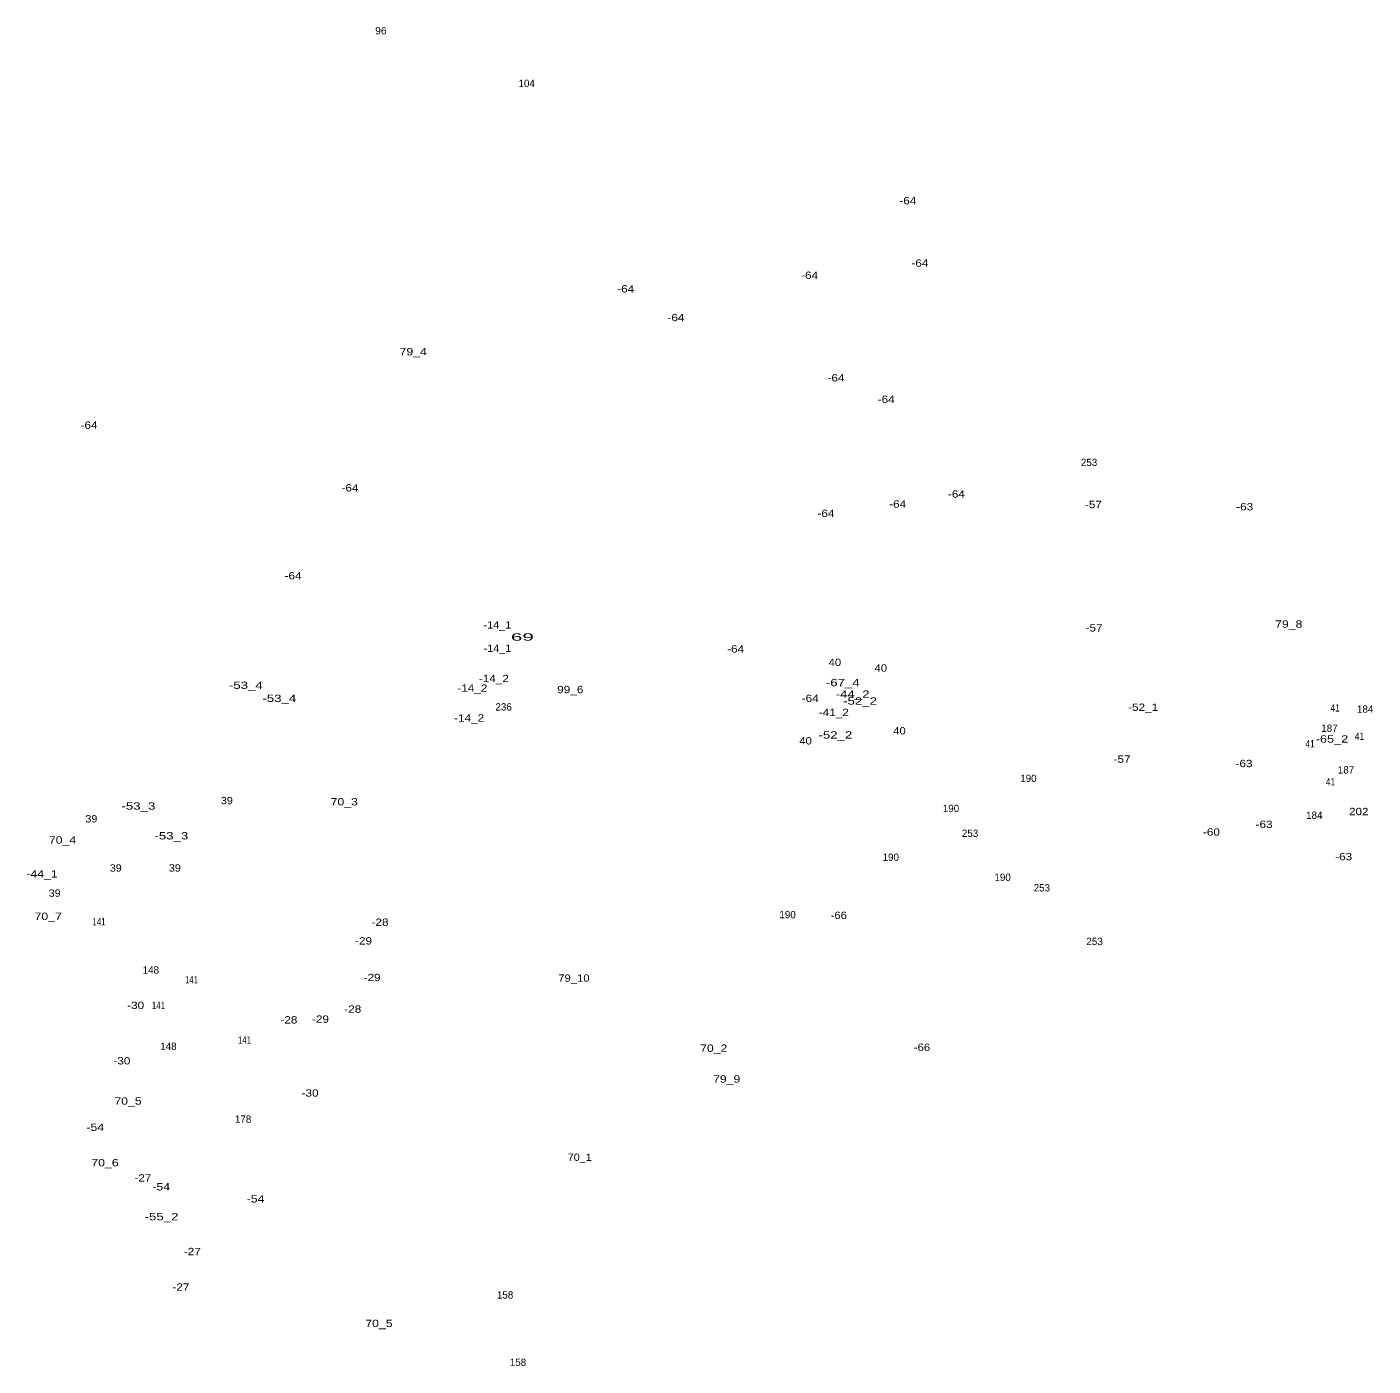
# Model space of a CAD drawing. Extents: x -659306 to -656317, y -989614 to -987663.
# Drawn here: x -657051 to -656317, y -988607 to -987877 of the extents above; entities that cross this region are included whole.
import ezdxf
from ezdxf.enums import TextEntityAlignment as Align

# ---------------------------------------------------------------- set-up
doc = ezdxf.new("R2010")
doc.units = 0
doc.header["$LTSCALE"] = 1.6
doc.layers.add('24', color=7, linetype='Continuous')

msp = doc.modelspace()

# ---------------------------------------------------------------- texts
at = {"layer": '24'}
for s, width, p in [('96', 1.05, (-656858.05, -987880.65)), ('-64', 1.2, (-656570.601, -987973.32)), ('-64', 1.2, (-656564.03, -988007.36)), ('-64', 1.2, (-656624.171, -988014.01)), ('-64', 1.2, (-656724.481, -988021.44)), ('-64', 1.2, (-656697.111, -988037.09)), ('79_4', 1.25, (-656840.4, -988055.66)), ('-64', 1.2, (-656609.78, -988069.95)), ('-64', 1.2, (-656582.41, -988081.69)), ('-64', 1.2, (-657017.28, -988095.76)), ('-64', 1.2, (-656874.9, -988129.96)), ('-64', 1.2, (-656544.091, -988133.32)), ('-64', 1.2, (-656576.15, -988138.8)), ('-57', 1.2, (-656469.39, -988139.04)), ('-63', 1.2, (-656386.82, -988140.24)), ('-64', 1.2, (-656615.26, -988143.89)), ('-64', 1.2, (-656905.981, -988177.88)), ('-14_1', 1.1, (-656794.459, -988204.73)), ('-57', 1.2, (-656469, -988206.32)), ('79_8', 1.25, (-656362.8, -988204.24)), ('69', 2.1, (-656780.871, -988211.31)), ('-14_1', 1.1, (-656794.459, -988217.46)), ('-64', 1.2, (-656664.53, -988217.82)), ('40', 1.15, (-656610.37, -988225.1)), ('40', 1.15, (-656585.34, -988228.22)), ('-53_4', 1.35, (-656931.75, -988237.61)), ('-14_2', 1.2, (-656808.16, -988239.2)), ('-14_2', 1.2, (-656796.419, -988233.91)), ('-67_4', 1.35, (-656606.091, -988236.16)), ('-53_4', 1.35, (-656913.47, -988244.75)), ('99_6', 1.2, (-656754.73, -988239.96)), ('-64', 1.2, (-656623.861, -988244.78)), ('-44_2', 1.35, (-656600.71, -988242.48)), ('-52_2', 1.35, (-656596.679, -988246.19)), ('-41_2', 1.2, (-656610.98, -988252.43)), ('-52_1', 1.2, (-656442.22, -988249.6)), ('41', 0.85, (-656337.48, -988249.95)), ('-14_2', 1.2, (-656809.929, -988255.46)), ('40', 1.15, (-656626.4, -988267.93)), ('-52_2', 1.35, (-656610.12, -988264.72)), ('40', 1.15, (-656575.169, -988262.45)), ('-65_2', 1.3, (-656339.22, -988266.9)), ('41', 0.85, (-656324.179, -988265.4)), ('41', 0.85, (-656351.169, -988269.51)), ('-57', 1.2, (-656453.75, -988277.91)), ('-63', 1.2, (-656387.21, -988280.29)), ('41', 0.85, (-656340.02, -988290.24)), ('-53_3', 1.35, (-656990.319, -988303.48)), ('39', 1.1, (-656942.09, -988300.48)), ('70_3', 1.25, (-656878.04, -988301.15)), ('39', 1.1, (-657016, -988310.45)), ('202', 1.2, (-656324.62, -988306.48)), ('-53_3', 1.35, (-656972.34, -988319.71)), ('-60', 1.2, (-656405, -988317.64)), ('-63', 1.2, (-656376.26, -988313.44)), ('70_4', 1.25, (-657031.72, -988321.97)), ('-63', 1.2, (-656332.85, -988331.05)), ('-44_1', 1.25, (-657042.89, -988340.5)), ('39', 1.1, (-657002.7, -988337.25)), ('39', 1.1, (-656970.44, -988337.25)), ('39', 1.1, (-657036, -988350.97)), ('70_7', 1.25, (-657039.54, -988363.63)), ('-66', 1.15, (-656608.24, -988363.1)), ('141', 0.8, (-657011.829, -988366.56)), ('-28', 1.2, (-656858.52, -988366.84)), ('-29', 1.2, (-656867.52, -988377.02)), ('141', 0.8, (-656961.38, -988398.25)), ('-29', 1.2, (-656862.82, -988397)), ('79_10', 1.15, (-656752.74, -988397.32)), ('-30', 1.2, (-656991.83, -988412.2)), ('141', 0.8, (-656979.419, -988412.26)), ('-28', 1.2, (-656873.39, -988414.23)), ('-28', 1.2, (-656908.24, -988420.1)), ('-29', 1.2, (-656891.01, -988419.71)), ('141', 0.8, (-656932.439, -988431.11)), ('70_2', 1.25, (-656676.47, -988435.54)), ('-66', 1.15, (-656562.88, -988435.08)), ('-30', 1.2, (-656999.33, -988442.42)), ('79_9', 1.25, (-656669.43, -988452.36)), ('70_5', 1.25, (-656995.99, -988464.36)), ('-30', 1.2, (-656896.68, -988459.98)), ('-54', 1.25, (-657013.88, -988478.69)), ('70_1', 1.1, (-656749.59, -988495)), ('70_6', 1.25, (-657008.57, -988497.99)), ('-27', 1.2, (-656987.91, -988506.29)), ('-54', 1.25, (-656977.9, -988511.16)), ('-54', 1.25, (-656926.43, -988517.74)), ('-55_2', 1.35, (-656977.709, -988527.42)), ('-27', 1.2, (-656960.89, -988546.44)), ('-27', 1.2, (-656967.15, -988565.83)), ('70_5', 1.25, (-656859.12, -988585.64))]:
    msp.add_text(s, height=4, dxfattribs=dict(at, width=width)).set_placement(p, align=Align.CENTER)
for s, p in [('104', (-656778.51, -987909.37)), ('253', (-656471.707, -988116.08)), ('236', (-656791.113, -988249.42)), ('184', (-656321.1, -988250.6)), ('187', (-656340.581, -988261.07)), ('190', (-656504.811, -988288.37)), ('187', (-656331.591, -988283.76)), ('190', (-656547.041, -988304.8)), ('184', (-656348.87, -988308.5)), ('253', (-656536.627, -988318.34)), ('190', (-656579.89, -988331.4)), ('190', (-656518.88, -988342.36)), ('253', (-656497.477, -988348.08)), ('190', (-656636.201, -988362.7)), ('253', (-656468.737, -988377.33)), ('148', (-656983.53, -988392.9)), ('148', (-656973.949, -988434.56)), ('178', (-656933.231, -988474.23)), ('158', (-656790.29, -988570.09)), ('158', (-656783.25, -988606.86))]:
    msp.add_text(s, height=4, dxfattribs=at).set_placement(p, align=Align.CENTER)

doc.saveas('drawing.dxf')
